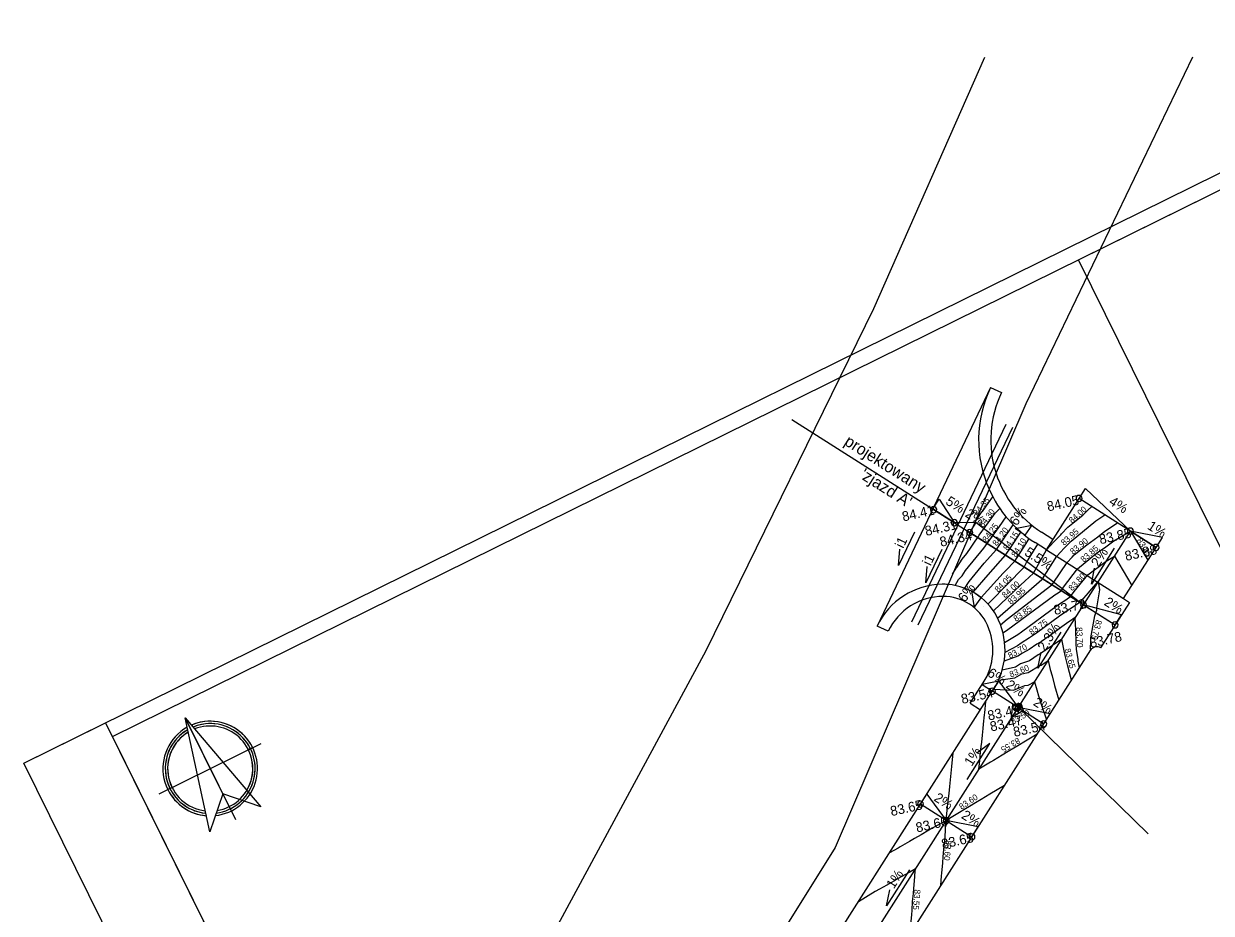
# Model space of a CAD drawing. Extents: x 6441746 to 6441901, y 5798263 to 5798406.
# Drawn here: x 6441745.6 to 6441843.1, y 5798333 to 5798406 of the extents above; entities that cross this region are included whole.
import ezdxf

# ---------------------------------------------------------------- set-up
doc = ezdxf.new("R2010")
doc.units = 0
for name, color, linetype in [('GEPINN', 7, 'Continuous'), ('GEPPGD', 7, 'Continuous'), ('GESBWT', 7, 'Continuous'), ('GESDZI', 7, 'Continuous'), ('GESDZI_O', 7, 'Continuous'), ('GSLBRA', 7, 'Continuous'), ('GSLKOC', 7, 'Continuous'), ('GSLKOU', 7, 'Continuous'), ('GSLOGS', 7, 'Continuous'), ('GSLPRZ', 7, 'Continuous'), ('GSLSKN', 7, 'Continuous'), ('GSLWSD', 7, 'Continuous'), ('GSPDIP', 7, 'Continuous'), ('GSPDLP', 7, 'Continuous'), ('GSPINN', 7, 'Continuous'), ('GSPPIK', 7, 'Continuous')]:
    doc.layers.add(name, color=color, linetype=linetype)

# ---------------------------------------------------------------- blocks, each defined once
blk = doc.blocks.new('_DotSmall')
for start, end in [(0, 180), (180, 0)]:
    blk.add_arc((0, 0), 0.0625, start, end)
blk = doc.blocks.new('A$C720754CC')
at = {"layer": 'GSPDIP'}
blk.add_lwpolyline([(-0.092, -0.352), (0.354, 0.05), (0.086, 0.347), (-0.359, -0.055)], close=True, dxfattribs=at)
blk.add_lwpolyline([(0.005, -0.265), (-0.263, 0.032), (-0.134, 0.149), (0.134, -0.149), (0.246, -0.048), (-0.022, 0.249)], dxfattribs=at)

msp = doc.modelspace()

# ---------------------------------------------------------------- linework, layer by layer
at = {"layer": 'GEPINN'}
for p, q in [((6441824.979, 5798376.147), (6441815.69, 5798356.566)), ((6441824.979, 5798376.147), (6441825.898, 5798375.753)), ((6441818.522, 5798356.912), (6441826.281, 5798373.154)), ((6441819.063, 5798356.654), (6441826.822, 5798372.895)), ((6441829.577, 5798362.832), (6441835.912, 5798358.817)), ((6441816.593, 5798356.136), (6441815.69, 5798356.566))]:
    msp.add_line(p, q, dxfattribs=at)
for centre, radius, start, end in [((6441834.014, 5798371.861), 10, 154.62158, 203.98143), ((6441834.014, 5798371.861), 9, 154.38107, 197.77072), ((6441821.111, 5798353.995), 6, 90.91253, 154.62162), ((6441821.095, 5798354.995), 5, 85.1683, 90.91253), ((6441821.111, 5798353.995), 5, 90.19309, 154.62162)]:
    msp.add_arc(centre, radius, start, end, dxfattribs=at)
at = {"layer": 'GESBWT'}
for p, q in [((6441830.114, 5798363.675), (6441829.183, 5798364.268)), ((6441836.402, 5798358.506), (6441834.031, 5798354.779)), ((6441823.328, 5798350.214), (6441824.401, 5798351.902)), ((6441823.328, 5798350.214), (6441824.172, 5798349.677))]:
    msp.add_line(p, q, dxfattribs=at)
for centre, radius, start, end in [((6441834.014, 5798371.861), 9, 197.77072, 237.53667), ((6441821.095, 5798354.995), 4, 90.01384, 90.91253), ((6441821.095, 5798354.995), 4, 24.16342, 90.01384), ((6441820.183, 5798354.585), 5, 327.53667, 24.1629)]:
    msp.add_arc(centre, radius, start, end, dxfattribs=at)
at = {"layer": 'GESDZI'}
for p, q in [((6441829.577, 5798362.832), (6441832.261, 5798367.05)), ((6441838.589, 5798363.025), (6441832.261, 5798367.05)), ((6441829.577, 5798362.832), (6441828.646, 5798363.424)), ((6441835.912, 5798358.817), (6441838.589, 5798363.025)), ((6441835.912, 5798358.817), (6441836.402, 5798358.506)), ((6441811.358, 5798320.221), (6441833.228, 5798354.598)), ((6441803.361, 5798316.966), (6441825.245, 5798351.365))]:
    msp.add_line(p, q, dxfattribs=at)
for centre, radius, start, end in [((6441834.014, 5798371.861), 10, 203.98143, 237.53667), ((6441821.095, 5798354.995), 5, 24.15824, 85.1683), ((6441820.183, 5798354.585), 6, 327.53667, 24.15867), ((6441833.725, 5798354.262), 0.6, 57.53667, 147.53667)]:
    msp.add_arc(centre, radius, start, end, dxfattribs=at)
at = {"layer": 'GSLBRA'}
for p, q in [((6441758.861, 5798349.036), (6441762.988, 5798340.677)), ((6441756.745, 5798342.793), (6441765.104, 5798346.92))]:
    msp.add_line(p, q, dxfattribs=at)
for points in [[(6441745.614, 5798345.296), (6441868.651, 5798406.04), (6441900.746, 5798341.031), (6441777.709, 5798280.287)], [(6441752.892, 5798347.495), (6441868.083, 5798404.366), (6441899.072, 5798341.599), (6441783.881, 5798284.728)], [(6441832.216, 5798386.658), (6441868.083, 5798404.366), (6441899.072, 5798341.599), (6441863.205, 5798323.891)], [(6441758.861, 5798349.036), (6441765.077, 5798341.709), (6441761.956, 5798342.767)], [(6441758.861, 5798349.036), (6441765.077, 5798341.709), (6441761.956, 5798342.767), (6441760.898, 5798339.645)]]:
    msp.add_lwpolyline(points, close=True, dxfattribs=at)
for points in [[(6441759.382, 5798348.421), (6441759.514, 5798348.266)], [(6441759.118, 5798347.849), (6441759.075, 5798348.049)], [(6441764.233, 5798346.49), (6441764.059, 5798346.404)], [(6441764.233, 5798346.49), (6441764.407, 5798346.576)], [(6441757.616, 5798343.223), (6441757.442, 5798343.137)], [(6441757.616, 5798343.223), (6441757.79, 5798343.309)], [(6441763.926, 5798343.065), (6441764.059, 5798342.909)], [(6441760.607, 5798340.985), (6441760.564, 5798341.184)]]:
    msp.add_lwpolyline(points, dxfattribs=at)
for radius, start, end in [(3.884, 276.38002, 113.39178), (3.884, 26.27593, 113.39178), (3.69, 26.27593, 112.47309), (3.69, 277.79978, 112.47309), (3.496, 279.40144, 111.44467), (3.884, 119.16008, 265.31929), (3.69, 120.08071, 264.39866), (3.69, 120.08071, 206.27593), (3.496, 121.10719, 263.37218), (3.496, 121.10719, 206.27593), (3.496, 329.17968, 26.27593), (3.69, 328.15125, 26.27593), (3.884, 206.27593, 265.31929), (3.69, 206.27593, 264.39866)]:
    msp.add_arc((6441760.924, 5798344.856), radius, start, end, dxfattribs=at)
at = {"layer": 'GSLKOC'}
for points in [[(6441757.985, 5798279.781), (6441785.979, 5798325.557), (6441801.634, 5798354.549), (6441815.402, 5798382.645), (6441824.514, 5798403.306)], [(6441841.564, 5798403.306), (6441827.893, 5798374.814), (6441812.231, 5798338.37), (6441797.846, 5798315.309), (6441786.869, 5798297.713), (6441764.868, 5798263.306)]]:
    msp.add_lwpolyline(points, dxfattribs=at)
at = {"layer": 'GSLKOU'}
for points in [[(6441832.216, 5798386.658), (6441868.083, 5798404.366), (6441899.072, 5798341.599), (6441863.205, 5798323.891)], [(6441745.614, 5798345.296), (6441752.339, 5798348.616), (6441784.434, 5798283.607), (6441777.709, 5798280.287)]]:
    msp.add_lwpolyline(points, close=True, dxfattribs=at)
at = {"layer": 'GSLPRZ'}
for points in [[(6441823.734, 5798365.132), (6441824.284, 5798365.938), (6441824.321, 5798365.978), (6441824.828, 5798366.682), (6441825.181, 5798367.172)], [(6441822.083, 5798359.896), (6441822.372, 5798360.383), (6441822.419, 5798360.448), (6441822.651, 5798360.676), (6441822.94, 5798361.129), (6441824.434, 5798362.947), (6441824.706, 5798363.346), (6441825.719, 5798364.727), (6441826.278, 5798365.523)], [(6441831.609, 5798363.546), (6441833.645, 5798365.193), (6441834.368, 5798365.709)], [(6441823.562, 5798359.344), (6441824.796, 5798360.76), (6441826.231, 5798362.375), (6441826.679, 5798363.062), (6441827.494, 5798364.278)], [(6441832.136, 5798361.276), (6441833.682, 5798362.558), (6441834.458, 5798363.061), (6441835.121, 5798363.572), (6441836.475, 5798364.368), (6441837.915, 5798361.966)], [(6441824.781, 5798358.373), (6441824.925, 5798358.511), (6441827.754, 5798361.406), (6441827.959, 5798361.776), (6441828.875, 5798363.278)], [(6441825.577, 5798357.213), (6441829.199, 5798360.386), (6441829.271, 5798360.441), (6441830.429, 5798362.313), (6441830.752, 5798362.649), (6441831.02, 5798362.929), (6441831.262, 5798363.184), (6441831.609, 5798363.546)], [(6441826.015, 5798355.992), (6441826.313, 5798356.202), (6441830.275, 5798359.115), (6441830.41, 5798359.207), (6441830.802, 5798359.467), (6441830.992, 5798359.747), (6441832.136, 5798361.276)], [(6441833.96, 5798359.524), (6441833.85, 5798360.234), (6441833.843, 5798360.238), (6441833.264, 5798359.598), (6441833, 5798359.278), (6441832.439, 5798358.647), (6441832.318, 5798358.502), (6441831.918, 5798358.232), (6441831.713, 5798358.087), (6441831.29, 5798357.8), (6441831.089, 5798357.667), (6441830.66, 5798357.376), (6441828.762, 5798355.98), (6441828.205, 5798355.589), (6441827.518, 5798355.16), (6441827.199, 5798354.938), (6441826.18, 5798354.398)], [(6441833.226, 5798354.596), (6441833.211, 5798354.756), (6441833.209, 5798354.803), (6441833.239, 5798355.24), (6441833.223, 5798355.594), (6441833.545, 5798357.411), (6441833.639, 5798357.655), (6441833.721, 5798357.855), (6441833.724, 5798358.048), (6441833.96, 5798359.524)], [(6441824.376, 5798358.193), (6441824.384, 5798358.202)], [(6441831.642, 5798352.106), (6441831.303, 5798353.373), (6441831.133, 5798354.15), (6441831.006, 5798354.655), (6441830.836, 5798355.495), (6441830.165, 5798355.023), (6441830.07, 5798354.964), (6441829.158, 5798354.332), (6441828.91, 5798354.2), (6441828.19, 5798353.717), (6441827.464, 5798353.451), (6441827.036, 5798353.191), (6441825.952, 5798352.939)], [(6441825.247, 5798351.368), (6441826.884, 5798351.304), (6441827.803, 5798351.667), (6441828.071, 5798351.706), (6441828.6, 5798351.98), (6441828.782, 5798351.322), (6441828.943, 5798350.828), (6441829.196, 5798349.979), (6441829.581, 5798348.866)], [(6441828.83, 5798347.685), (6441827.871, 5798347.109), (6441827.231, 5798346.725), (6441826.912, 5798346.533), (6441826.432, 5798346.245), (6441825.953, 5798345.958), (6441825.235, 5798345.526), (6441824.995, 5798345.383), (6441824.036, 5798344.807), (6441824.133, 5798345.734), (6441824.152, 5798345.919), (6441824.228, 5798346.661), (6441824.266, 5798347.031), (6441824.324, 5798347.587), (6441824.382, 5798348.143), (6441824.42, 5798348.514), (6441824.497, 5798349.256), (6441824.516, 5798349.441), (6441824.612, 5798350.369)], [(6441818.363, 5798331.232), (6441818.528, 5798332.835), (6441818.553, 5798333.234), (6441818.596, 5798333.927), (6441818.664, 5798334.589), (6441818.707, 5798334.996), (6441818.766, 5798335.955), (6441818.775, 5798336.088), (6441818.829, 5798336.622), (6441818.369, 5798336.346), (6441818.252, 5798336.282), (6441817.409, 5798335.822), (6441817.058, 5798335.611), (6441816.487, 5798335.268), (6441815.879, 5798334.937), (6441815.527, 5798334.745), (6441814.143, 5798333.914)]]:
    msp.add_lwpolyline(points, dxfattribs=at)
at = {"layer": 'GSLWSD'}
for p, q in [((6441808.677, 5798373.542), (6441835.224, 5798356.654)), ((6441795.423, 5798299.831), (6441836.479, 5798364.366))]:
    msp.add_line(p, q, dxfattribs=at)
at = {"layer": 'GSPDLP'}
for points in [[(6441821.878, 5798360.817), (6441822.181, 5798361.328), (6441822.187, 5798361.336), (6441822.215, 5798361.364), (6441822.653, 5798362.047), (6441823.048, 5798362.529), (6441823.399, 5798363.041), (6441823.737, 5798363.531), (6441823.945, 5798363.831), (6441824.07, 5798364.021), (6441825.109, 5798365.445), (6441825.368, 5798365.825), (6441825.751, 5798366.227)], [(6441831.345, 5798364.682), (6441832.566, 5798365.67), (6441832.994, 5798366.076), (6441833.314, 5798366.38)], [(6441831.814, 5798365.061), (6441832.566, 5798365.67), (6441832.994, 5798366.076), (6441833.314, 5798366.38)], [(6441831.873, 5798362.411), (6441832.891, 5798363.235), (6441833.795, 5798363.879), (6441834.374, 5798364.36), (6441835.422, 5798365.039)], [(6441822.879, 5798359.666), (6441823.228, 5798360.21), (6441824.476, 5798361.73), (6441825.472, 5798362.858), (6441826.623, 5798364.543), (6441826.851, 5798364.883)], [(6441825.234, 5798357.799), (6441827.482, 5798359.954), (6441827.803, 5798360.26), (6441828.518, 5798360.92), (6441829.576, 5798362.832), (6441830.166, 5798363.448), (6441830.22, 5798363.504), (6441830.756, 5798364.065), (6441830.825, 5798364.137), (6441831.345, 5798364.682)], [(6441824.225, 5798358.894), (6441826.036, 5798360.903), (6441826.214, 5798361.101), (6441826.988, 5798361.893), (6441827.922, 5798363.331), (6441828.174, 5798363.744)], [(6441825.815, 5798356.654), (6441826.353, 5798357.126), (6441830.036, 5798359.954), (6441830.122, 5798360.093), (6441831.283, 5798361.794), (6441831.699, 5798362.23), (6441831.873, 5798362.411)], [(6441832.99, 5798360.757), (6441834.482, 5798361.905), (6441835.159, 5798362.303), (6441835.163, 5798362.301), (6441836.602, 5798359.902)], [(6441826.151, 5798355.201), (6441827.225, 5798355.871), (6441827.538, 5798356.091), (6441830.467, 5798358.245), (6441830.75, 5798358.437), (6441831.097, 5798358.667), (6441831.288, 5798358.797), (6441831.557, 5798358.987), (6441831.864, 5798359.404), (6441832.99, 5798360.757)], [(6441823.782, 5798358.567), (6441823.789, 5798358.574)], [(6441831.953, 5798357.252), (6441831.482, 5798356.932), (6441831.429, 5798356.897), (6441830.853, 5798356.506), (6441829.986, 5798355.869), (6441829.185, 5798355.306), (6441828.794, 5798355.062), (6441828.178, 5798354.635), (6441827.621, 5798354.34), (6441827.241, 5798354.084), (6441826.113, 5798353.671)], [(6441832.299, 5798353.137), (6441832.195, 5798353.667), (6441832.183, 5798353.844), (6441832.054, 5798354.638), (6441832.035, 5798355.124), (6441832.017, 5798355.31), (6441831.99, 5798356.139), (6441831.998, 5798356.255), (6441831.953, 5798357.252)], [(6441826.985, 5798352.32), (6441827.576, 5798352.626), (6441828.077, 5798352.743), (6441828.981, 5798353.291), (6441829.14, 5798353.349), (6441829.718, 5798353.738), (6441829.897, 5798352.987), (6441830.04, 5798352.486), (6441830.248, 5798351.677), (6441830.612, 5798350.486)], [(6441825.655, 5798352.124), (6441826.985, 5798352.32)], [(6441826.72, 5798349.026), (6441826.836, 5798350.138), (6441826.836, 5798350.14), (6441826.847, 5798350.139), (6441827.482, 5798350.223), (6441827.662, 5798349.66), (6441827.661, 5798349.657), (6441827.679, 5798349.601), (6441827.519, 5798349.505), (6441826.72, 5798349.026)], [(6441826.146, 5798343.466), (6441824.947, 5798342.746), (6441824.228, 5798342.315), (6441823.749, 5798342.027), (6441823.27, 5798341.74), (6441822.95, 5798341.548), (6441822.311, 5798341.165), (6441821.352, 5798340.589), (6441821.468, 5798341.701), (6441821.497, 5798341.979), (6441821.583, 5798342.813), (6441821.64, 5798343.369), (6441821.698, 5798343.925), (6441821.784, 5798344.759), (6441821.813, 5798345.037), (6441821.929, 5798346.152)], [(6441820.924, 5798335.257), (6441820.98, 5798336.049), (6441820.994, 5798336.256), (6441821.084, 5798337.122), (6441821.114, 5798337.601), (6441821.152, 5798338.214), (6441821.228, 5798338.952), (6441821.262, 5798339.283), (6441821.326, 5798340.321), (6441821.33, 5798340.374), (6441821.352, 5798340.589), (6441821.168, 5798340.477), (6441821.121, 5798340.451), (6441820.207, 5798339.953), (6441819.922, 5798339.782), (6441819.286, 5798339.4), (6441818.748, 5798339.106), (6441818.327, 5798338.876), (6441817.581, 5798338.428), (6441817.399, 5798338.327), (6441816.705, 5798337.941)]]:
    msp.add_lwpolyline(points, dxfattribs=at)
at = {"layer": 'GSPINN'}
msp.add_line((6441827.426, 5798349.762), (6441837.924, 5798339.488), dxfattribs=at)
at = {"layer": 'GSPPIK'}
for points in [[(6441836.479, 5798364.366), (6441832.261, 5798367.05), (6441832.781, 5798367.868)], [(6441822.022, 5798365.052), (6441820.25, 5798366.179), (6441820.771, 5798366.998)], [(6441822.022, 5798365.052), (6441823.288, 5798364.247), (6441823.808, 5798365.065)], [(6441832.625, 5798358.307), (6441823.288, 5798364.247), (6441823.808, 5798365.065)], [(6441828.377, 5798364.845), (6441827.802, 5798364.022), (6441827.007, 5798364.578)], [(6441836.479, 5798364.366), (6441838.589, 5798363.025), (6441839.109, 5798363.843)], [(6441823.648, 5798358.077), (6441824.224, 5798358.893), (6441823.432, 5798359.452)], [(6441832.625, 5798358.307), (6441835.224, 5798356.654), (6441835.744, 5798357.472)], [(6441824.304, 5798351.748), (6441825.147, 5798351.212), (6441825.667, 5798352.03)], [(6441827.257, 5798349.87), (6441825.148, 5798351.211), (6441825.669, 5798352.029)], [(6441827.257, 5798349.87), (6441829.366, 5798348.528), (6441829.886, 5798349.347)], [(6441821.353, 5798340.589), (6441819.244, 5798341.93), (6441819.765, 5798342.748)], [(6441821.353, 5798340.589), (6441823.461, 5798339.247), (6441823.982, 5798340.065)]]:
    msp.add_lwpolyline(points, close=True, dxfattribs=at)
for points in [[(6441818.738, 5798364.288), (6441817.437, 5798361.546), (6441817.535, 5798362.883)], [(6441820.982, 5798362.86), (6441819.682, 5798360.118), (6441819.779, 5798361.455)], [(6441835.156, 5798362.967), (6441833.278, 5798360.015), (6441833.539, 5798361.329)], [(6441830.756, 5798356.051), (6441828.878, 5798353.099), (6441829.139, 5798354.413)], [(6441823.063, 5798343.958), (6441824.941, 5798346.91), (6441823.861, 5798346.116)], [(6441818.342, 5798336.537), (6441816.464, 5798333.585), (6441816.725, 5798334.899)]]:
    msp.add_lwpolyline(points, dxfattribs=at)

# ---------------------------------------------------------------- block references
at = {"layer": 'GSLSKN', "xscale": 4, "yscale": 4}
for p in [(6441832.261, 5798367.05), (6441820.335, 5798366.126), (6441822.022, 5798365.052), (6441823.288, 5798364.247), (6441836.479, 5798364.366), (6441838.589, 5798363.025), (6441832.625, 5798358.307), (6441835.224, 5798356.654), (6441825.148, 5798351.212), (6441827.257, 5798349.87), (6441829.366, 5798348.528), (6441819.243, 5798341.931), (6441821.353, 5798340.589), (6441823.462, 5798339.247)]:
    msp.add_blockref('_DotSmall', p, dxfattribs=at)
at = {"layer": 'GSPINN', "rotation": -164.4116379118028}
msp.add_blockref('A$C720754CC', (6441827.257, 5798349.87), dxfattribs=at)

# ---------------------------------------------------------------- texts
at = {"layer": 'GEPPGD'}
for s, rotation, p in [('84.35', 50.62332, (6441823.908, 5798365.584)), ('84.25', 54.15353, (6441824.688, 5798363.416)), ('84.15', 55.76699, (6441826.396, 5798362.723)), ('83.95', 41.57461, (6441831.037, 5798363.145)), ('83.85', 41.57461, (6441832.652, 5798361.762)), ('83.85', 302.23924, (6441836.965, 5798363.595)), ('84.05', 45.65469, (6441825.626, 5798359.295)), ('83.95', 41.22445, (6441826.663, 5798358.298)), ('83.85', 36.30226, (6441827.097, 5798356.892)), ('83.75', 35.3744, (6441828.377, 5798355.797)), ('83.75', 254.99221, (6441833.673, 5798357.113)), ('83.65', 285.48838, (6441831.062, 5798354.643)), ('83.55', 210.97751, (6441827.225, 5798347.425)), ('83.55', 265.12687, (6441818.75, 5798334.939))]:
    msp.add_text(s, height=0.5, rotation=rotation, dxfattribs=at).set_placement(p)
at = {"layer": 'GESDZI_O'}
for s, p in [('projektowany ', (6441812.906, 5798371.501)), ("'zjazd A'", (6441814.19, 5798368.769))]:
    msp.add_text(s, height=0.96, rotation=327.53667, dxfattribs=at).set_placement(p)
at = {"layer": 'GSLOGS'}
for s, rotation, p in [('84.30', 53.17784, (6441824.381, 5798364.617)), ('84.00', 41.63481, (6441831.687, 5798364.968)), ('84.20', 53.17784, (6441825.5, 5798363.098)), ('84.10', 57.66308, (6441827.075, 5798362.174)), ('83.90', 39.3519, (6441831.764, 5798362.412)), ('84.00', 41.22445, (6441826.182, 5798358.83)), ('83.80', 47.61943, (6441831.709, 5798359.406)), ('83.70', 272.22289, (6441832.031, 5798356.458)), ('83.70', 29.04223, (6441826.596, 5798353.876)), ('83.60', 21.39885, (6441826.661, 5798352.332)), ('83.50', 30.09587, (6441826.835, 5798348.442)), ('83.60', 33.71114, (6441822.617, 5798341.456)), ('83.60', 265.56407, (6441821.29, 5798338.985))]:
    msp.add_text(s, height=0.5, rotation=rotation, dxfattribs=at).set_placement(p)
at = {"layer": 'GSLSKN'}
for s, p in [('84.05', (6441829.719, 5798365.975)), ('84.41', (6441817.827, 5798365.151)), ('84.31', (6441819.703, 5798363.958)), ('84.34', (6441820.92, 5798363.071)), ('83.85', (6441834.007, 5798363.273)), ('83.88', (6441836.112, 5798361.908)), ('83.72', (6441830.272, 5798357.465)), ('83.78', (6441833.223, 5798354.766)), ('83.54', (6441822.672, 5798350.158)), ('83.49', (6441824.843, 5798348.794)), ('83.47', (6441825.045, 5798347.894)), ('83.54', (6441826.955, 5798347.45)), ('83.65', (6441816.861, 5798340.943)), ('83.60', (6441818.95, 5798339.596)), ('83.65', (6441821.06, 5798338.254))]:
    msp.add_text(s, height=0.8, rotation=12.53667, dxfattribs=at).set_placement(p)
at = {"layer": 'GSPPIK'}
for s, rotation, p in [('5%', 327.53667, (6441821.241, 5798366.615)), ('4%', 327.53667, (6441834.643, 5798366.601)), ('2%', 327.53667, (6441822.846, 5798365.594)), ('6%', 55.07847, (6441827.138, 5798364.734)), ('1%', 327.53667, (6441837.806, 5798364.588)), ('i1', 64.62162, (6441817.828, 5798362.89)), ('5.5%', 327.53667, (6441827.715, 5798362.434)), ('i1', 64.62162, (6441820.072, 5798361.462)), ('2%', 57.53667, (6441833.863, 5798361.352)), ('6%', 54.79661, (6441822.901, 5798358.464)), ('2%', 327.53667, (6441834.258, 5798358.334)), ('2.3%', 57.53667, (6441829.463, 5798354.435)), ('6%', 327.53668, (6441824.655, 5798352.513)), ('2%', 327.53667, (6441826.186, 5798351.539)), ('2%', 327.53667, (6441828.439, 5798350.106)), ('1%', 57.53667, (6441823.451, 5798344.984)), ('2%', 327.53667, (6441820.282, 5798342.258)), ('2%', 327.53667, (6441822.534, 5798340.825)), ('1%', 57.53667, (6441817.049, 5798334.922))]:
    msp.add_text(s, height=0.8, rotation=rotation, dxfattribs=at).set_placement(p)

doc.saveas('drawing.dxf')
